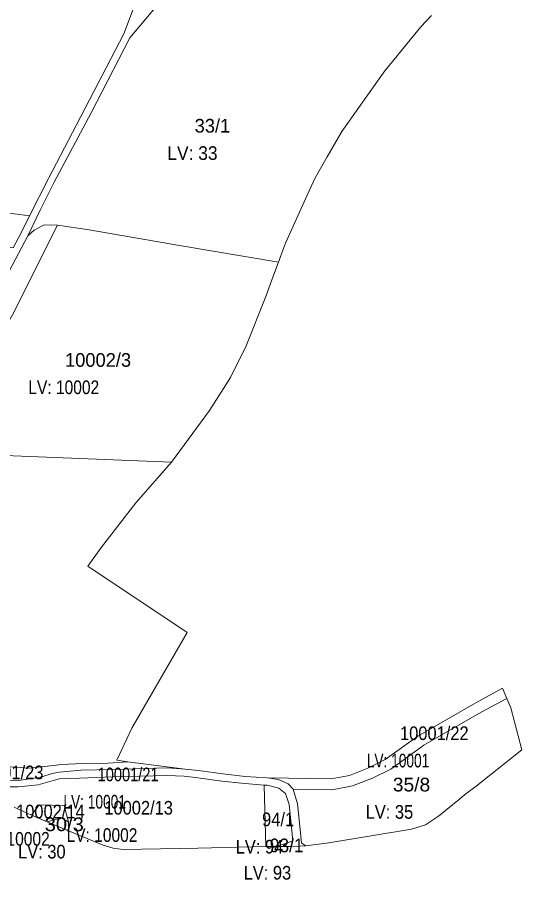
# Model space of a CAD drawing. Extents: x -713758 to -711119, y -1123067 to -1120789.
# Drawn here: x -711834 to -711465, y -1122829 to -1122197 of the extents above; entities that cross this region are included whole.
import ezdxf
from ezdxf.enums import TextEntityAlignment as Align

# ---------------------------------------------------------------- set-up
doc = ezdxf.new("R2010")
doc.units = 0
doc.header["$LTSCALE"] = 4
doc.layers.add('10', color=7, linetype='Continuous', lineweight=13)
doc.layers.add('11', color=7, linetype='Continuous')
doc.layers.add('13', color=7, linetype='Continuous')

msp = doc.modelspace()

# ---------------------------------------------------------------- linework, layer by layer
at = {"layer": '10'}
for points in [[(-711748.73, -1122189.21), (-711756.25, -1122209.29), (-711790.84, -1122275.82), (-711811.42, -1122315.11), (-711825.23, -1122342.57), (-711975.57, -1122322.4), (-712125.91, -1122302.23), (-712276.25, -1122282.06), (-712285.91, -1122338.46), (-712316.81, -1122334.14), (-712352.47, -1122329.56)], [(-711854.46, -1122409.42), (-711826.6, -1122357.07), (-711817.55, -1122338.42), (-711807.32, -1122317.99), (-711780.19, -1122267.09), (-711751.85, -1122212.21), (-711732.41, -1122188.95)], [(-711748.73, -1122189.21), (-711756.25, -1122209.29), (-711790.84, -1122275.82), (-711811.42, -1122315.11), (-711825.23, -1122342.57), (-711831.51, -1122355.06), (-711837.26, -1122366.02)], [(-711732.41, -1122188.95), (-711751.85, -1122212.21), (-711780.19, -1122267.09), (-711807.32, -1122317.99), (-711817.55, -1122338.42), (-711826.6, -1122357.07), (-711822, -1122352.93), (-711814.7, -1122349.21), (-711804.85, -1122349.26), (-711781.6, -1122352.87), (-711715.62, -1122364.24), (-711643.19, -1122376.47), (-711642.72, -1122375.21), (-711641.62, -1122372.26), (-711638.02, -1122362.63), (-711622.15, -1122327.42), (-711616.44, -1122314.74), (-711607.5, -1122299.31), (-711596.76, -1122280.77), (-711565.45, -1122236.29), (-711556.4, -1122225.3), (-711548.99, -1122216.31), (-711538.98, -1122204.15), (-711531.33, -1122195.96)], [(-711898.41, -1122515.73), (-711721.48, -1122522.77), (-711747.44, -1122552.71), (-711772.58, -1122585.14), (-711782.61, -1122599.01), (-711709.93, -1122647.42), (-711750.43, -1122717.46), (-711761.55, -1122741.04), (-711753.34, -1122742.09), (-711767.78, -1122743.12), (-711786.72, -1122743.48), (-711801.68, -1122744.21), (-711825.18, -1122746.95), (-711850.37, -1122745.1)], [(-711852.47, -1122755.55), (-711833.73, -1122755.85), (-711818.59, -1122753.72), (-711815.57, -1122753.05), (-711808.7, -1122750.82), (-711803.45, -1122749.67), (-711787.77, -1122748.29), (-711764.52, -1122747.72), (-711724.48, -1122746.65), (-711711.49, -1122747.45), (-711753.34, -1122742.09), (-711767.78, -1122743.12), (-711786.72, -1122743.48), (-711801.68, -1122744.21), (-711825.18, -1122746.95), (-711850.37, -1122745.1)], [(-711850.1, -1122760.54), (-711833.51, -1122760.45), (-711818.97, -1122759.05), (-711807.09, -1122755.59), (-711803.37, -1122754.76), (-711788.78, -1122754.07), (-711764.44, -1122753.24), (-711724.83, -1122752.21), (-711712.19, -1122752.72), (-711702.14, -1122753.86), (-711684.67, -1122756.34), (-711667.81, -1122757.97), (-711653.71, -1122759.19), (-711651.46, -1122759.38), (-711643.06, -1122761.46), (-711638.06, -1122765.31), (-711635.5, -1122773.49), (-711632.77, -1122800.11), (-711633.76, -1122804.06), (-711623.56, -1122803.78), (-711626.28, -1122801.38), (-711629.35, -1122772.98), (-711632.51, -1122762.23), (-711636.21, -1122758.22), (-711643.22, -1122755.2), (-711651.47, -1122753.87), (-711667.51, -1122753.01), (-711683.82, -1122751.07), (-711701.66, -1122748.47), (-711711.49, -1122747.45), (-711724.48, -1122746.65), (-711764.52, -1122747.72), (-711787.77, -1122748.29), (-711803.45, -1122749.67), (-711808.7, -1122750.82), (-711815.57, -1122753.05), (-711818.59, -1122753.72), (-711833.73, -1122755.85), (-711852.47, -1122755.55)], [(-711850.1, -1122760.54), (-711833.51, -1122760.45), (-711818.97, -1122759.05), (-711807.09, -1122755.59), (-711803.37, -1122754.76), (-711788.78, -1122754.07), (-711764.44, -1122753.24), (-711724.83, -1122752.21), (-711712.19, -1122752.72), (-711702.14, -1122753.86), (-711684.67, -1122756.34), (-711667.81, -1122757.97), (-711653.71, -1122759.19), (-711652.46, -1122804.28), (-711702.11, -1122805.28), (-711756.88, -1122806.31), (-711764.06, -1122805.39), (-711771.44, -1122803.17), (-711796.83, -1122792.59), (-711796.76, -1122786.33), (-711799.88, -1122774.22), (-711818.17, -1122773.63), (-711823.99, -1122781.13), (-711836.65, -1122775.48)]]:
    msp.add_lwpolyline(points, dxfattribs=at)
for points in [[(-712285.91, -1122338.46), (-712276.25, -1122282.06), (-712125.91, -1122302.23), (-711975.57, -1122322.4), (-711825.23, -1122342.57), (-711831.51, -1122355.06), (-711837.26, -1122366.02), (-711839.35, -1122365.76), (-711929.12, -1122354.6), (-712056.43, -1122342.27), (-712189.95, -1122324.89), (-712194.64, -1122351.21)], [(-711908.34, -1122515.33), (-711906.19, -1122511), (-711876.86, -1122453.09), (-711854.46, -1122409.42), (-711826.6, -1122357.07), (-711822, -1122352.93), (-711814.7, -1122349.21), (-711804.85, -1122349.26), (-711837.82, -1122415.02), (-711858.74, -1122451.35), (-711896.67, -1122513.04), (-711898.41, -1122515.73)], [(-711898.41, -1122515.73), (-711896.67, -1122513.04), (-711858.74, -1122451.35), (-711837.82, -1122415.02), (-711804.85, -1122349.26), (-711781.6, -1122352.87), (-711715.62, -1122364.24), (-711643.19, -1122376.47), (-711648.03, -1122389.42), (-711652.39, -1122401.55), (-711666.77, -1122437.7), (-711678.35, -1122460.76), (-711693.66, -1122485.02), (-711721.48, -1122522.77)], [(-711651.47, -1122753.87), (-711643.22, -1122755.2), (-711636.21, -1122758.22), (-711632.51, -1122762.23), (-711604.06, -1122762.76), (-711588.97, -1122759.81), (-711574.51, -1122754.12), (-711560.94, -1122747.48), (-711536.98, -1122730.1), (-711495, -1122705.91), (-711476.24, -1122695.72), (-711479.4, -1122688.33), (-711498.88, -1122698.92), (-711541.34, -1122723.38), (-711565.08, -1122740.6), (-711577.74, -1122746.79), (-711591.22, -1122752.1), (-711604.76, -1122754.74)], [(-711632.51, -1122762.23), (-711629.35, -1122772.98), (-711626.28, -1122801.38), (-711623.56, -1122803.78), (-711606.39, -1122801.45), (-711545.95, -1122791.41), (-711535.66, -1122788.34), (-711526.25, -1122782), (-711510.89, -1122769.53), (-711507.16, -1122766.45), (-711498.67, -1122760.01), (-711465.28, -1122733.42), (-711473.23, -1122702.74), (-711476.24, -1122695.72), (-711495, -1122705.91), (-711536.98, -1122730.1), (-711560.94, -1122747.48), (-711574.51, -1122754.12), (-711588.97, -1122759.81), (-711604.06, -1122762.76)], [(-711653.71, -1122759.19), (-711652.46, -1122804.28), (-711649.39, -1122804.22), (-711644.45, -1122804.17), (-711632.77, -1122800.11), (-711635.5, -1122773.49), (-711638.06, -1122765.31), (-711643.06, -1122761.46), (-711651.46, -1122759.38)], [(-711823.99, -1122781.13), (-711812.36, -1122786.04), (-711802.05, -1122783.17), (-711796.76, -1122786.33), (-711799.88, -1122774.22), (-711818.17, -1122773.63)], [(-711812.36, -1122786.04), (-711796.83, -1122792.59), (-711796.76, -1122786.33), (-711802.05, -1122783.17)], [(-711644.45, -1122804.17), (-711633.76, -1122804.06), (-711632.77, -1122800.11)]]:
    msp.add_lwpolyline(points, close=True, dxfattribs=at)

# ---------------------------------------------------------------- texts
at = {"layer": '11'}
for s, p in [('33/1', (-711691.52, -1122281.58)), ('10002/3', (-711775.19, -1122453.03))]:
    msp.add_text(s, height=10, dxfattribs=at).set_placement(p, align=Align.CENTER)
for s, width, p in [('10001/22', 0.9, (-711529.22, -1122726.25)), ('10001/23', 0.9, (-711840.231, -1122754.94)), ('10001/21', 0.8, (-711753.22, -1122756.43)), ('35/8', 1.05, (-711545.91, -1122763.87)), ('10002/14', 0.9, (-711810.08, -1122783.57)), ('10002/13', 0.9, (-711745.51, -1122780.81)), ('94/1', 0.9, (-711643.49, -1122789.34)), ('30/3', 1.1, (-711799.92, -1122792.94)), ('93/1', 0.95, (-711637.23, -1122808.37))]:
    msp.add_text(s, height=10, dxfattribs=dict(at, width=width)).set_placement(p, align=Align.CENTER)
at = {"layer": '13'}
for s, width, p in [('LV: 33 ', 0.95, (-711704.37, -1122301.58)), ('LV: 10002 ', 0.85, (-711798.713, -1122473.03)), ('LV: 10001 ', 0.75, (-711554.382, -1122746.25)), ('LV: 10001 ', 0.75, (-711776.274, -1122776.43)), ('LV: 35 ', 0.9, (-711560.4, -1122783.87)), ('LV: 10002 ', 0.85, (-711770.74, -1122800.81)), ('LV: 10002 ', 0.85, (-711834.874, -1122803.57)), ('LV: 30 ', 0.9, (-711814.643, -1122812.94)), ('LV: 94 ', 0.9, (-711655.468, -1122809.34)), ('LV: 93 ', 0.9, (-711649.644, -1122828.37))]:
    msp.add_text(s, height=10, dxfattribs=dict(at, width=width)).set_placement(p, align=Align.CENTER)

doc.saveas('drawing.dxf')
